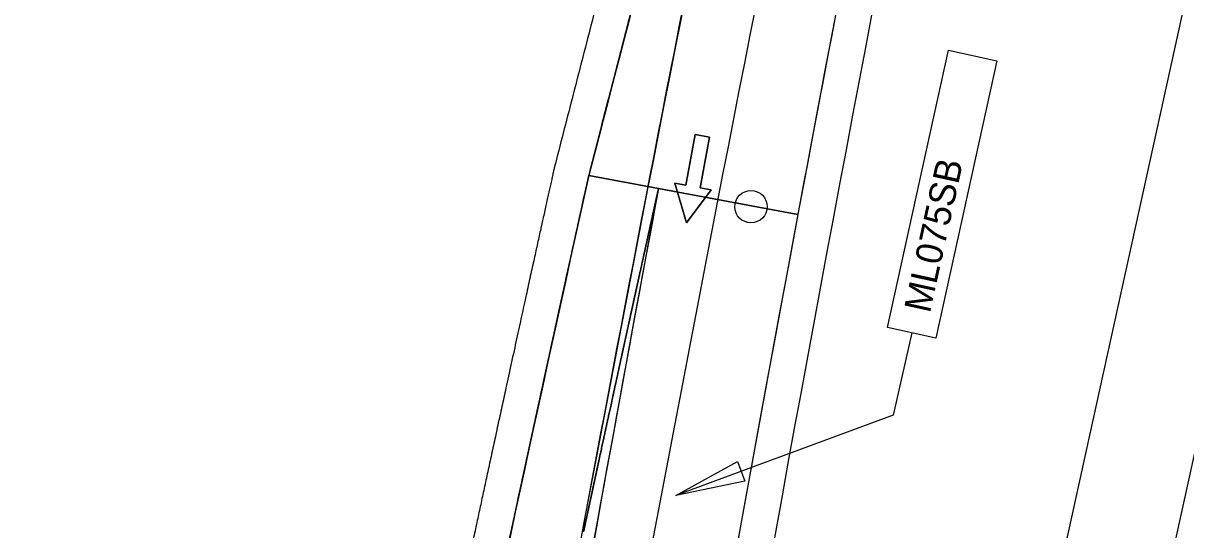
# Model space of a CAD drawing. Extents: x 14104283 to 14120882, y 8635219 to 8671666.
# Drawn here: x 14107950.2 to 14108147, y 8640609 to 8640694.8 of the extents above; entities that cross this region are included whole.
import ezdxf

# ---------------------------------------------------------------- set-up
doc = ezdxf.new("R2010")
doc.units = 0
for name, color, linetype in [('Cell', 7, 'Continuous'), ('dsnPaintPlaceBrokenLineWhite', 7, 'Continuous'), ('dsnPaintPlaceEdgeLineRightWhite', 7, 'Continuous'), ('dsnPaintRemoveDoubleCenterLineYellow', 7, 'Continuous'), ('dsnShadingPaved', 7, 'Continuous'), ('dsnStgShadingPrevPav', 7, 'Continuous'), ('Text', 7, 'Continuous')]:
    doc.layers.add(name, color=color, linetype=linetype)

msp = doc.modelspace()

# ---------------------------------------------------------------- linework, layer by layer
at = {"layer": 'Cell'}
msp.add_lwpolyline([(14108063.89, 8640675.97), (14108066.35, 8640675.52), (14108064.79, 8640666.91), (14108066.63, 8640666.58), (14108062.44, 8640660.99), (14108060.48, 8640667.69), (14108062.33, 8640667.36)], close=True, dxfattribs=at)
msp.add_lwpolyline([(14108062.33, 8640667.36), (14108060.48, 8640667.69), (14108062.44, 8640660.99), (14108066.63, 8640666.58), (14108064.79, 8640666.91), (14108066.35, 8640675.52), (14108063.89, 8640675.97), (14108062.33, 8640667.36)], dxfattribs=at)
msp.add_circle((14108073.37, 8640663.73), 2.75, dxfattribs=at)
at = {"layer": 'dsnPaintPlaceBrokenLineWhite'}
msp.add_arc((14117394.14, 8638857.08), 9500, 167.610212, 171.325989, dxfattribs=at)
at = {"layer": 'dsnPaintPlaceEdgeLineRightWhite'}
for centre, radius, start, end in [((14117245.13, 8638308.71), 9497.18, 164.578206, 165.609485), ((14117342.69, 8638609.63), 9522.13, 167.509575, 168.915877)]:
    msp.add_arc(centre, radius, start, end, dxfattribs=at)
at = {"layer": 'dsnPaintRemoveDoubleCenterLineYellow'}
msp.add_line((14108099.08, 8640397.01), (14108306.37, 8641340.66), dxfattribs=at)
at = {"layer": 'dsnShadingPaved'}
for centre, radius, start, end in [((14117394.14, 8638857.08), 9512, 167.610212, 171.325989), ((14117394.14, 8638857.08), 9500, 167.610212, 171.325989), ((14117502.5, 8638839.63), 9621.75, 168.048489, 169.460498), ((14117245.13, 8638308.71), 9497.18, 164.591267, 165.609485), ((14117342.69, 8638609.63), 9522.13, 167.509575, 168.915877)]:
    msp.add_arc(centre, radius, start, end, dxfattribs=at)
at = {"layer": 'dsnStgShadingPrevPav'}
for p, q in [((14108045.92, 8640669.04), (14108057.72, 8640666.84)), ((14108081.31, 8640662.43), (14108045.92, 8640669.04)), ((14108057.72, 8640666.84), (14108081.31, 8640662.43))]:
    msp.add_line(p, q, dxfattribs=at)
msp.add_lwpolyline([(14108081.5, 8640400.87), (14108123.34, 8640591.33), (14108126.55, 8640605.98), (14108216.67, 8641016.2), (14108268.16, 8641250.61), (14108382.95, 8641773.15), (14108422.02, 8641764.57), (14108309.38, 8641251.8), (14108270.22, 8641073.55), (14108265.93, 8641054.01), (14108255.74, 8641007.62), (14108202.1, 8640763.44), (14108120.56, 8640392.29)], close=True, dxfattribs=at)
for radius, start, end in [(9488, 167.610212, 172.222077), (9482, 167.610212, 172.222077), (9488, 168.328257, 169.413861), (9512, 169.413861, 172.222077), (9512, 169.413861, 170.574102), (9488, 169.413861, 172.222077)]:
    msp.add_arc((14117407.82, 8638919.35), radius, start, end, dxfattribs=at)
for points, degree in [([(14108045.92, 8640669.04), (14108046.67, 8640671.96), (14108048.17, 8640677.8), (14108050.43, 8640686.55), (14108052.7, 8640695.31), (14108054.98, 8640704.06), (14108057.26, 8640712.8), (14108059.55, 8640721.55), (14108061.85, 8640730.29), (14108064.16, 8640739.03), (14108066.48, 8640747.76), (14108068.81, 8640756.5), (14108071.14, 8640765.23), (14108073.48, 8640773.95), (14108075.83, 8640782.68), (14108078.19, 8640791.4), (14108080.55, 8640800.12), (14108082.93, 8640808.84), (14108085.31, 8640817.55), (14108087.7, 8640826.26), (14108090.1, 8640834.97), (14108091.7, 8640840.77), (14108092.51, 8640843.67)], 3), ([(14108045.92, 8640669.04), (14108046.67, 8640671.96), (14108048.17, 8640677.8), (14108050.43, 8640686.55), (14108052.7, 8640695.31), (14108054.98, 8640704.06), (14108057.26, 8640712.8), (14108059.55, 8640721.55), (14108061.85, 8640730.29), (14108064.16, 8640739.03), (14108066.48, 8640747.76), (14108068.81, 8640756.5), (14108071.14, 8640765.23), (14108073.48, 8640773.95), (14108075.83, 8640782.68), (14108078.19, 8640791.4), (14108080.55, 8640800.12), (14108082.93, 8640808.84), (14108085.31, 8640817.55), (14108087.7, 8640826.26), (14108090.1, 8640834.97), (14108091.7, 8640840.77), (14108092.51, 8640843.67)], 3), ([(14108070.77, 8640786.95), (14108070.25, 8640785.01), (14108069.2, 8640781.13), (14108067.63, 8640775.31), (14108066.07, 8640769.49), (14108064.51, 8640763.67), (14108062.96, 8640757.84), (14108061.41, 8640752.02), (14108059.86, 8640746.19), (14108058.31, 8640740.36), (14108056.77, 8640734.54), (14108055.23, 8640728.71), (14108053.7, 8640722.87), (14108052.17, 8640717.04), (14108050.64, 8640711.21), (14108049.12, 8640705.37), (14108047.6, 8640699.54), (14108046.09, 8640693.7), (14108044.58, 8640687.86), (14108043.07, 8640682.02), (14108041.56, 8640676.18), (14108040.56, 8640672.28), (14108040.06, 8640670.34)], 3), ([(14108040.07, 8640670.33), (14108039.11, 8640666.01), (14108035.79, 8640651.03), (14108029.85, 8640623.7), (14108025.19, 8640602.04), (14108020.26, 8640578.84), (14108015.47, 8640556.04), (14108010.72, 8640533.12), (14108006.03, 8640510.22), (14108001.39, 8640487.29), (14107996.81, 8640464.36), (14107992.28, 8640441.41), (14107987.82, 8640418.46), (14107983.4, 8640395.49), (14107979.05, 8640372.51), (14107974.75, 8640349.53), (14107970.51, 8640326.51), (14107966.33, 8640303.59), (14107962.15, 8640280.24), (14107958.29, 8640258.43), (14107953.48, 8640230.88), (14107950.9, 8640215.75), (14107950.15, 8640211.39)], 2), ([(14107956.07, 8640210.37), (14107957.38, 8640218.06), (14107960.02, 8640233.43), (14107964.04, 8640256.47), (14107968.11, 8640279.5), (14107972.24, 8640302.51), (14107976.42, 8640325.52), (14107980.66, 8640348.51), (14107984.96, 8640371.49), (14107989.32, 8640394.46), (14107993.73, 8640417.41), (14107998.19, 8640440.35), (14108002.71, 8640463.28), (14108007.29, 8640486.2), (14108011.92, 8640509.1), (14108016.61, 8640531.99), (14108021.36, 8640554.87), (14108026.16, 8640577.73), (14108031.01, 8640600.58), (14108035.93, 8640623.41), (14108040.89, 8640646.24), (14108044.25, 8640661.44), (14108045.92, 8640669.04)], 3), ([(14108045.67, 8640667.9), (14108045.76, 8640668.28), (14108045.84, 8640668.66), (14108045.92, 8640669.04)], 2), ([(14108045.17, 8640665.62), (14108045.34, 8640666.38), (14108045.5, 8640667.14), (14108045.67, 8640667.9)], 2), ([(14108057.72, 8640666.84), (14108057.64, 8640666.46), (14108057.55, 8640666.08), (14108057.47, 8640665.7)], 2), ([(14108057.47, 8640665.7), (14108057.55, 8640666.08), (14108057.64, 8640666.46), (14108057.72, 8640666.84)], 2), ([(14108044.67, 8640663.34), (14108044.75, 8640663.72), (14108044.83, 8640664.1), (14108044.92, 8640664.48)], 2), ([(14108044.92, 8640664.48), (14108045, 8640664.86), (14108045.09, 8640665.24), (14108045.17, 8640665.62)], 2), ([(14108057.22, 8640664.56), (14108057.13, 8640664.18), (14108057.05, 8640663.8), (14108056.97, 8640663.42)], 2), ([(14108056.97, 8640663.42), (14108057.05, 8640663.8), (14108057.13, 8640664.18), (14108057.22, 8640664.56)], 2), ([(14108057.47, 8640665.7), (14108057.38, 8640665.32), (14108057.3, 8640664.94), (14108057.22, 8640664.56)], 2), ([(14108057.22, 8640664.56), (14108057.3, 8640664.94), (14108057.38, 8640665.32), (14108057.47, 8640665.7)], 2), ([(14108043.91, 8640659.92), (14108044.16, 8640661.06), (14108044.41, 8640662.2), (14108044.67, 8640663.34)], 2), ([(14108056.71, 8640662.28), (14108056.46, 8640661.14), (14108056.21, 8640660), (14108055.96, 8640658.87)], 2), ([(14108055.96, 8640658.87), (14108056.21, 8640660), (14108056.46, 8640661.14), (14108056.71, 8640662.28)], 2), ([(14108056.97, 8640663.42), (14108056.88, 8640663.04), (14108056.8, 8640662.66), (14108056.71, 8640662.28)], 2), ([(14108056.71, 8640662.28), (14108056.8, 8640662.66), (14108056.88, 8640663.04), (14108056.97, 8640663.42)], 2), ([(14108043.41, 8640657.64), (14108043.49, 8640658.02), (14108043.58, 8640658.4), (14108043.66, 8640658.78)], 2), ([(14108043.66, 8640658.78), (14108043.74, 8640659.16), (14108043.83, 8640659.54), (14108043.91, 8640659.92)], 2), ([(14108055.96, 8640658.87), (14108055.88, 8640658.49), (14108055.79, 8640658.11), (14108055.71, 8640657.73)], 2), ([(14108055.71, 8640657.73), (14108055.79, 8640658.11), (14108055.88, 8640658.49), (14108055.96, 8640658.87)], 2), ([(14108042.91, 8640655.36), (14108043.07, 8640656.12), (14108043.24, 8640656.88), (14108043.41, 8640657.64)], 2), ([(14108055.71, 8640657.73), (14108055.21, 8640655.45), (14108054.7, 8640653.17), (14108054.2, 8640650.89)], 2), ([(14108054.2, 8640650.89), (14108054.7, 8640653.17), (14108055.21, 8640655.45), (14108055.71, 8640657.73)], 2), ([(14108042.15, 8640651.94), (14108042.4, 8640653.08), (14108042.65, 8640654.22), (14108042.91, 8640655.36)], 2), ([(14108041.65, 8640649.66), (14108041.74, 8640650.04), (14108041.82, 8640650.42), (14108041.9, 8640650.8)], 2), ([(14108041.9, 8640650.8), (14108041.99, 8640651.18), (14108042.07, 8640651.56), (14108042.15, 8640651.94)], 2), ([(14108054.2, 8640650.89), (14108054.12, 8640650.51), (14108054.04, 8640650.13), (14108053.95, 8640649.75)], 2), ([(14108053.95, 8640649.75), (14108054.04, 8640650.13), (14108054.12, 8640650.51), (14108054.2, 8640650.89)], 2), ([(14108041.15, 8640647.37), (14108041.23, 8640647.76), (14108041.32, 8640648.14), (14108041.4, 8640648.52)], 2), ([(14108041.4, 8640648.52), (14108041.48, 8640648.9), (14108041.57, 8640649.28), (14108041.65, 8640649.66)], 2), ([(14108053.7, 8640648.62), (14108053.62, 8640648.24), (14108053.54, 8640647.86), (14108053.45, 8640647.48)], 2), ([(14108053.45, 8640647.48), (14108053.54, 8640647.86), (14108053.62, 8640648.24), (14108053.7, 8640648.62)], 2), ([(14108053.95, 8640649.75), (14108053.87, 8640649.37), (14108053.79, 8640648.99), (14108053.7, 8640648.62)], 2), ([(14108053.7, 8640648.62), (14108053.79, 8640648.99), (14108053.87, 8640649.37), (14108053.95, 8640649.75)], 2), ([(14108040.9, 8640646.23), (14108040.98, 8640646.61), (14108041.07, 8640646.99), (14108041.15, 8640647.37)], 2), ([(14108053.45, 8640647.48), (14108053.29, 8640646.72), (14108053.12, 8640645.96), (14108052.95, 8640645.2)], 2), ([(14108052.95, 8640645.2), (14108053.12, 8640645.96), (14108053.29, 8640646.72), (14108053.45, 8640647.48)], 2), ([(14108039.9, 8640641.67), (14108040.15, 8640642.81), (14108040.4, 8640643.95), (14108040.65, 8640645.09)], 2), ([(14108040.65, 8640645.09), (14108040.73, 8640645.47), (14108040.82, 8640645.85), (14108040.9, 8640646.23)], 2), ([(14108052.95, 8640645.2), (14108052.87, 8640644.82), (14108052.79, 8640644.44), (14108052.7, 8640644.06)], 2), ([(14108052.7, 8640644.06), (14108052.79, 8640644.44), (14108052.87, 8640644.82), (14108052.95, 8640645.2)], 2), ([(14108052.7, 8640644.06), (14108052.45, 8640642.92), (14108052.2, 8640641.78), (14108051.95, 8640640.64)], 2), ([(14108051.95, 8640640.64), (14108052.2, 8640641.78), (14108052.45, 8640642.92), (14108052.7, 8640644.06)], 2), ([(14108039.16, 8640638.25), (14108039.4, 8640639.39), (14108039.65, 8640640.53), (14108039.9, 8640641.67)], 2), ([(14108051.95, 8640640.64), (14108051.87, 8640640.26), (14108051.79, 8640639.88), (14108051.7, 8640639.5)], 2), ([(14108051.7, 8640639.5), (14108051.79, 8640639.88), (14108051.87, 8640640.26), (14108051.95, 8640640.64)], 2), ([(14108051.7, 8640639.5), (14108051.62, 8640639.12), (14108051.54, 8640638.74), (14108051.46, 8640638.36)], 2), ([(14108051.46, 8640638.36), (14108051.54, 8640638.74), (14108051.62, 8640639.12), (14108051.7, 8640639.5)], 2), ([(14108038.66, 8640635.97), (14108038.74, 8640636.35), (14108038.82, 8640636.73), (14108038.91, 8640637.11)], 2), ([(14108038.91, 8640637.11), (14108038.99, 8640637.49), (14108039.07, 8640637.87), (14108039.16, 8640638.25)], 2), ([(14108051.46, 8640638.36), (14108051.04, 8640636.46), (14108050.63, 8640634.56), (14108050.21, 8640632.66)], 2), ([(14108050.21, 8640632.66), (14108050.63, 8640634.56), (14108051.04, 8640636.46), (14108051.46, 8640638.36)], 2), ([(14108037.42, 8640630.26), (14108037.75, 8640631.78), (14108038.08, 8640633.3), (14108038.41, 8640634.83)], 2), ([(14108038.41, 8640634.83), (14108038.49, 8640635.21), (14108038.58, 8640635.59), (14108038.66, 8640635.97)], 2), ([(14108050.21, 8640632.66), (14108050.13, 8640632.28), (14108050.05, 8640631.9), (14108049.97, 8640631.52)], 2), ([(14108049.97, 8640631.52), (14108050.05, 8640631.9), (14108050.13, 8640632.28), (14108050.21, 8640632.66)], 2), ([(14108049.97, 8640631.52), (14108049.22, 8640628.11), (14108048.48, 8640624.69), (14108047.74, 8640621.27)], 2), ([(14108047.74, 8640621.27), (14108048.48, 8640624.69), (14108049.22, 8640628.11), (14108049.97, 8640631.52)], 2), ([(14108036.68, 8640626.84), (14108036.84, 8640627.6), (14108037.01, 8640628.36), (14108037.17, 8640629.12)], 2), ([(14108037.17, 8640629.12), (14108037.25, 8640629.5), (14108037.34, 8640629.88), (14108037.42, 8640630.26)], 2), ([(14108036.43, 8640625.7), (14108036.51, 8640626.08), (14108036.59, 8640626.46), (14108036.68, 8640626.84)], 2), ([(14108036.18, 8640624.55), (14108036.26, 8640624.93), (14108036.35, 8640625.32), (14108036.43, 8640625.7)], 2), ([(14108035.19, 8640619.99), (14108035.44, 8640621.13), (14108035.69, 8640622.27), (14108035.93, 8640623.41)], 2), ([(14108035.93, 8640623.41), (14108036.02, 8640623.79), (14108036.1, 8640624.17), (14108036.18, 8640624.55)], 2), ([(14108047.74, 8640621.27), (14108047.66, 8640620.89), (14108047.58, 8640620.51), (14108047.49, 8640620.13)], 2), ([(14108047.49, 8640620.13), (14108047.58, 8640620.51), (14108047.66, 8640620.89), (14108047.74, 8640621.27)], 2), ([(14108034.45, 8640616.56), (14108034.7, 8640617.71), (14108034.95, 8640618.85), (14108035.19, 8640619.99)], 2), ([(14108047.25, 8640618.99), (14108047.17, 8640618.61), (14108047.08, 8640618.23), (14108047, 8640617.85)], 2), ([(14108047, 8640617.85), (14108047.08, 8640618.23), (14108047.17, 8640618.61), (14108047.25, 8640618.99)], 2), ([(14108047.49, 8640620.13), (14108047.41, 8640619.75), (14108047.33, 8640619.37), (14108047.25, 8640618.99)], 2), ([(14108047.25, 8640618.99), (14108047.33, 8640619.37), (14108047.41, 8640619.75), (14108047.49, 8640620.13)], 2), ([(14108047, 8640617.85), (14108046.92, 8640617.47), (14108046.84, 8640617.09), (14108046.75, 8640616.71)], 2), ([(14108046.75, 8640616.71), (14108046.84, 8640617.09), (14108046.92, 8640617.47), (14108047, 8640617.85)], 2), ([(14108033.96, 8640614.28), (14108034.04, 8640614.66), (14108034.13, 8640615.04), (14108034.21, 8640615.42)], 2), ([(14108034.21, 8640615.42), (14108034.29, 8640615.8), (14108034.37, 8640616.18), (14108034.45, 8640616.56)], 2), ([(14108046.51, 8640615.57), (14108046.34, 8640614.81), (14108046.18, 8640614.05), (14108046.02, 8640613.29)], 2), ([(14108046.02, 8640613.29), (14108046.18, 8640614.05), (14108046.34, 8640614.81), (14108046.51, 8640615.57)], 2), ([(14108046.75, 8640616.71), (14108046.67, 8640616.33), (14108046.59, 8640615.95), (14108046.51, 8640615.57)], 2), ([(14108046.51, 8640615.57), (14108046.59, 8640615.95), (14108046.67, 8640616.33), (14108046.75, 8640616.71)], 2), ([(14108032.98, 8640609.71), (14108033.31, 8640611.24), (14108033.63, 8640612.76), (14108033.96, 8640614.28)], 2), ([(14108046.02, 8640613.29), (14108045.93, 8640612.91), (14108045.85, 8640612.53), (14108045.77, 8640612.15)], 2), ([(14108045.77, 8640612.15), (14108045.85, 8640612.53), (14108045.93, 8640612.91), (14108046.02, 8640613.29)], 2), ([(14108045.77, 8640612.15), (14108045.61, 8640611.39), (14108045.44, 8640610.62), (14108045.28, 8640609.86)], 2), ([(14108045.28, 8640609.86), (14108045.44, 8640610.62), (14108045.61, 8640611.39), (14108045.77, 8640612.15)], 2), ([(14108032.74, 8640608.57), (14108032.82, 8640608.95), (14108032.9, 8640609.33), (14108032.98, 8640609.71)], 2), ([(14108045.28, 8640609.86), (14108045.2, 8640609.48), (14108045.12, 8640609.1), (14108045.03, 8640608.72)], 2), ([(14108045.03, 8640608.72), (14108045.12, 8640609.1), (14108045.2, 8640609.48), (14108045.28, 8640609.86)], 2)]:
    msp.add_open_spline(points, degree=degree, dxfattribs=at)
at = {"layer": 'Text'}
for points in [[(14108096.48, 8640643.25), (14108106.8, 8640690.24), (14108115, 8640688.44), (14108104.68, 8640641.45)], [(14108096.48, 8640643.25), (14108106.8, 8640690.24), (14108115, 8640688.44), (14108104.68, 8640641.45)], [(14108060.64, 8640614.81), (14108071.11, 8640620.57), (14108072.34, 8640617.24)]]:
    msp.add_lwpolyline(points, close=True, dxfattribs=at)
msp.add_lwpolyline([(14108100.58, 8640642.35), (14108097.42, 8640628.4), (14108060.64, 8640614.81)], dxfattribs=at)

# ---------------------------------------------------------------- texts
msp.add_text('ML075SB', height=4.484, rotation=77.6078, dxfattribs=at).set_placement((14108103.65, 8640645.56))

doc.saveas('drawing.dxf')
